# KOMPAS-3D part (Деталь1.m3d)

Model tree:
1. Эскиз:2
2. Операция выдавливания:1
     Расстояние 1 = 20
3. Эскиз:3
4. Операция выдавливания:2
     Расстояние 1 = 20; Расстояние 2 = 60
5. Эскиз:4
6. Операция выдавливания:3
     Расстояние 1 = 20; Расстояние 2 = 25
7. Эскиз:5
8. Вырезать элемент выдавливания:1
     Расстояние 1 = 25
9. Эскиз:6
10. Операция выдавливания:4
     Расстояние 1 = 20; Расстояние 2 = 25
11. Эскиз:7
12. Операция выдавливания:5
     Расстояние 1 = 20; Расстояние 2 = 25
13. Эскиз:8
14. Вырезать элемент выдавливания:2
     Расстояние 1 = 25
15. Эскиз:10
16. Операция выдавливания:6
     Расстояние 1 = 60; Расстояние 2 = 25
17. Эскиз:11
18. Операция выдавливания:7
     Расстояние 1 = 60; Расстояние 2 = 60
19. Эскиз:12
20. Вырезать элемент выдавливания:4
     Расстояние 1 = 60
21. Эскиз:13
22. Вырезать элемент выдавливания:5
     Расстояние 1 = 10
